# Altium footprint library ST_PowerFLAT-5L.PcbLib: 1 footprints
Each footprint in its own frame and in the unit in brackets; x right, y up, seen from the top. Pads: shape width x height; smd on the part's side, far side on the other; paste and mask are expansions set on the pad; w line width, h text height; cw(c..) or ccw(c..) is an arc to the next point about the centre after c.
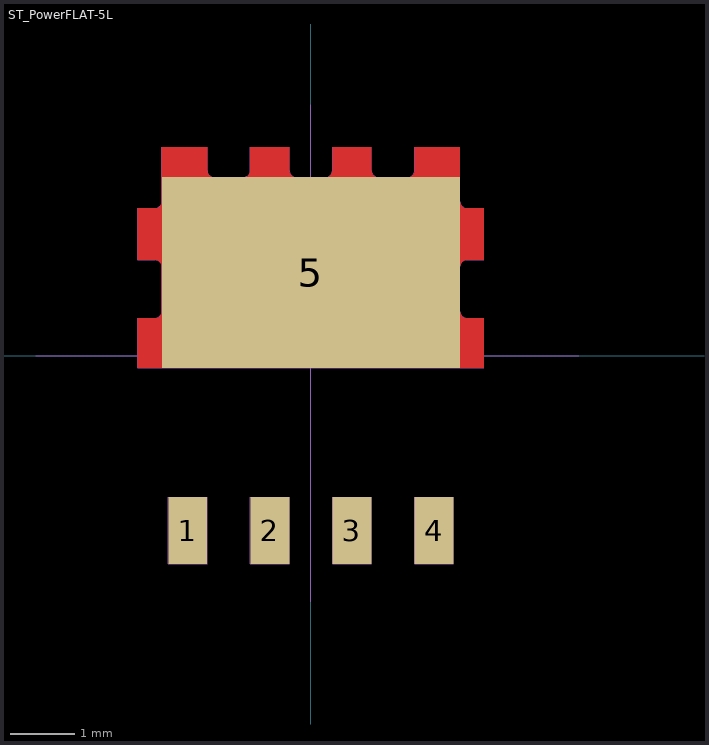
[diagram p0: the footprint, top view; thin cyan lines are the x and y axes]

## ST_PowerFLAT-5L [mm]
height 1
pads (5):
  rect 0.6x1.03 smd paste+0: 1(-1.905,-2.705) 2(-0.635,-2.705) 3(0.635,-2.705) 4(1.905,-2.705)
  rect 4.611x2.951 smd paste-20 mask-20: 5(0,1.285)
Top Layer:
  region: 196 vertices and 0 holes, not listed, extent -2.675,-0.19 2.676,3.221
Top Paste:
  rectangle: -2.625,-0.14 -1.655,0.53
  rectangle: -1.515,-0.14 -0.385,0.53
  rectangle: -0.245,-0.14 0.245,0.53
  rectangle: 0.385,-0.14 1.515,0.53
  rectangle: 1.655,-0.14 2.625,0.53
  rectangle: 1.655,0.67 2.255,1.39
  rectangle: 0.385,0.67 1.515,1.39
  rectangle: -0.245,0.67 0.245,1.39
  rectangle: -1.515,0.67 -0.385,1.39
  rectangle: -2.255,0.67 -1.655,1.39
  rectangle: -2.625,1.53 -1.655,2.23
  rectangle: -1.515,1.53 -0.385,2.23
  rectangle: -0.245,1.53 0.245,2.23
  rectangle: 0.385,1.53 1.515,2.23
  rectangle: 1.655,1.53 2.625,2.23
  rectangle: 1.655,2.37 2.255,3.17
  rectangle: 1.025,2.37 1.515,2.71
  rectangle: 0.385,2.37 0.885,3.17
  rectangle: -0.245,2.37 0.245,2.71
  rectangle: -0.885,2.37 -0.385,3.17
  rectangle: -1.515,2.37 -1.025,2.71
  rectangle: -2.255,2.37 -1.655,3.17
Mechanical 1:
  drawing of 304 lines, arcs and shapes, not listed
3D body "LCP154DJF.STEP": height 1.01, standoff -0.02, extent -2.6,-3.075 2.6,3.075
